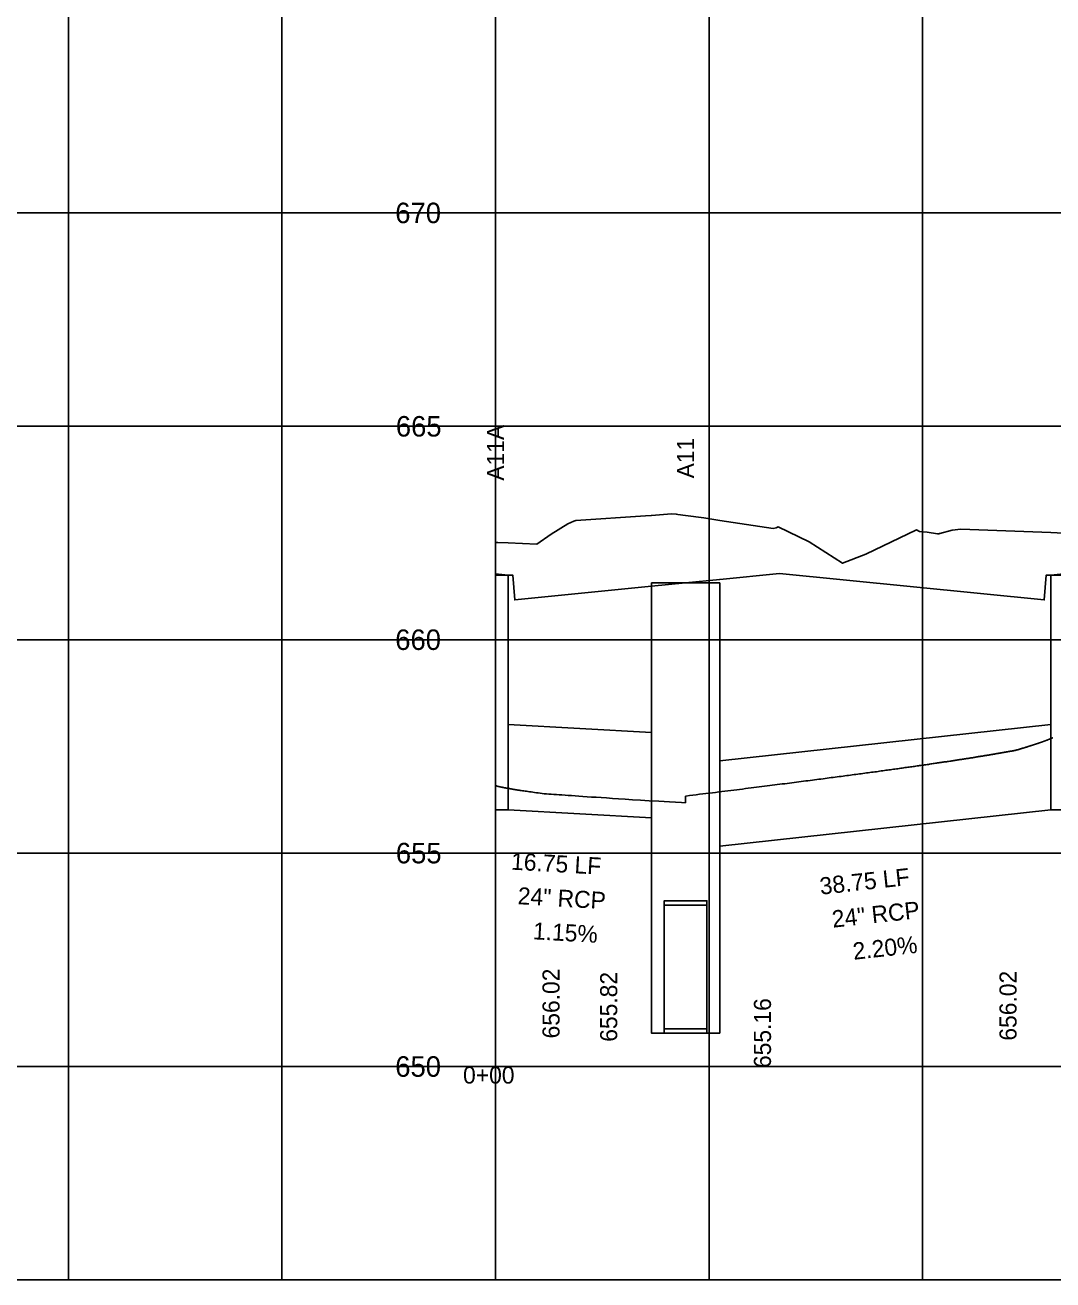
# Model space of a CAD drawing. Extents: x 2252703 to 2264864, y 13787568 to 13790989.
# Drawn here: x 2264558.6 to 2264678.9, y 13789015.9 to 13789162.9 of the extents above; entities that cross this region are included whole.
import ezdxf

# ---------------------------------------------------------------- set-up
doc = ezdxf.new("R2010")
doc.units = 0
for name, color, linetype in [('blank4', 7, 'Continuous'), ('BORD_grid_bottom_major_5int', 7, 'Continuous'), ('D_DRN_PROF_HGL', 7, 'Continuous'), ('D_PROF_1', 7, 'Continuous'), ('D_PROF_NOTES_1', 7, 'Continuous'), ('Default', 7, 'Continuous'), ('Drain_PipeInside', 7, 'Continuous'), ('E_Terrain', 7, 'Continuous'), ('Inlet', 7, 'Continuous'), ('z - Construction', 7, 'Continuous')]:
    doc.layers.add(name, color=color, linetype=linetype)

msp = doc.modelspace()

# ---------------------------------------------------------------- linework, layer by layer
at = {"layer": 'blank4'}
msp.add_lwpolyline([(2264613.67, 13789040.93), (2264613.67, 13789140.93), (2264701.42, 13789140.93), (2264701.42, 13789040.93)], close=True, dxfattribs=at)
at = {"layer": 'BORD_grid_bottom_major_5int'}
for p, q in [((2264563.67, 13789015.93), (2264563.67, 13789315.93)), ((2264588.67, 13789015.93), (2264588.67, 13789315.93)), ((2264613.67, 13789015.93), (2264613.67, 13789315.93)), ((2264638.67, 13789015.93), (2264638.67, 13789315.93)), ((2264663.67, 13789015.93), (2264663.67, 13789315.93)), ((2264413.67, 13789140.93), (2264763.67, 13789140.93)), ((2264413.67, 13789115.93), (2264763.67, 13789115.93)), ((2264413.67, 13789090.93), (2264763.67, 13789090.93)), ((2264413.67, 13789065.93), (2264763.67, 13789065.93)), ((2264413.67, 13789040.93), (2264763.67, 13789040.93)), ((2264413.67, 13789015.93), (2264763.67, 13789015.93))]:
    msp.add_line(p, q, dxfattribs=at)
at = {"layer": 'D_DRN_PROF_HGL'}
msp.add_line((2264635.92, 13789071.81), (2264635.92, 13789072.61), dxfattribs=at)
for points in [[(2264635.92, 13789072.61), (2264635.95, 13789072.62), (2264636.36, 13789072.67), (2264636.76, 13789072.72), (2264637.15, 13789072.77), (2264637.54, 13789072.82), (2264637.93, 13789072.86), (2264638.31, 13789072.91), (2264638.69, 13789072.96), (2264639.06, 13789073), (2264639.43, 13789073.05), (2264639.8, 13789073.09), (2264640.16, 13789073.14), (2264640.52, 13789073.18), (2264640.87, 13789073.23), (2264641.22, 13789073.27), (2264641.57, 13789073.31), (2264641.91, 13789073.36), (2264642.25, 13789073.4), (2264642.59, 13789073.44), (2264642.92, 13789073.48), (2264643.25, 13789073.52), (2264643.58, 13789073.56), (2264643.9, 13789073.61), (2264644.22, 13789073.65), (2264644.53, 13789073.69), (2264644.85, 13789073.72), (2264645.16, 13789073.76), (2264645.46, 13789073.8), (2264645.77, 13789073.84), (2264646.07, 13789073.88), (2264646.37, 13789073.92), (2264646.66, 13789073.95), (2264646.95, 13789073.99), (2264647.24, 13789074.03), (2264647.53, 13789074.06), (2264647.81, 13789074.1), (2264648.1, 13789074.14), (2264648.37, 13789074.17), (2264648.65, 13789074.21), (2264648.92, 13789074.24), (2264649.19, 13789074.28), (2264649.46, 13789074.31), (2264649.73, 13789074.35), (2264649.99, 13789074.38), (2264650.25, 13789074.41), (2264650.51, 13789074.45), (2264650.77, 13789074.48), (2264651.02, 13789074.51), (2264651.27, 13789074.55), (2264651.52, 13789074.58), (2264651.77, 13789074.61), (2264652.01, 13789074.64), (2264652.26, 13789074.67), (2264652.5, 13789074.71), (2264652.74, 13789074.74), (2264652.97, 13789074.77), (2264653.21, 13789074.8), (2264653.44, 13789074.83), (2264653.67, 13789074.86), (2264653.9, 13789074.89), (2264654.12, 13789074.92), (2264654.35, 13789074.95), (2264654.57, 13789074.98), (2264654.79, 13789075.01), (2264655.01, 13789075.04), (2264655.22, 13789075.07), (2264655.44, 13789075.09), (2264655.65, 13789075.12), (2264655.86, 13789075.15), (2264656.07, 13789075.18), (2264656.28, 13789075.21), (2264656.48, 13789075.23), (2264656.69, 13789075.26), (2264656.89, 13789075.29), (2264657.09, 13789075.32), (2264657.29, 13789075.34), (2264657.49, 13789075.37), (2264657.68, 13789075.4), (2264657.88, 13789075.42), (2264658.07, 13789075.45), (2264658.26, 13789075.47), (2264658.45, 13789075.5), (2264658.64, 13789075.53), (2264658.82, 13789075.55), (2264659.01, 13789075.58), (2264659.19, 13789075.6), (2264659.37, 13789075.63), (2264659.55, 13789075.65), (2264659.73, 13789075.68), (2264659.91, 13789075.7), (2264660.08, 13789075.73), (2264660.26, 13789075.75), (2264660.43, 13789075.77), (2264660.6, 13789075.8), (2264660.77, 13789075.82), (2264660.94, 13789075.84), (2264661.11, 13789075.87), (2264661.27, 13789075.89), (2264661.44, 13789075.91), (2264661.6, 13789075.94), (2264661.77, 13789075.96), (2264661.93, 13789075.98), (2264662.09, 13789076.01), (2264662.24, 13789076.03), (2264662.4, 13789076.05), (2264662.56, 13789076.07), (2264662.71, 13789076.09), (2264662.87, 13789076.12), (2264663.02, 13789076.14), (2264663.17, 13789076.16), (2264663.32, 13789076.18), (2264663.47, 13789076.2), (2264663.62, 13789076.22), (2264663.76, 13789076.25), (2264663.91, 13789076.27), (2264664.05, 13789076.29), (2264664.19, 13789076.31), (2264664.34, 13789076.33), (2264664.48, 13789076.35), (2264664.62, 13789076.37), (2264664.76, 13789076.39), (2264664.89, 13789076.41), (2264665.03, 13789076.43), (2264665.17, 13789076.45), (2264665.3, 13789076.47), (2264665.43, 13789076.49), (2264665.57, 13789076.51), (2264665.7, 13789076.53), (2264665.83, 13789076.55), (2264665.96, 13789076.57), (2264666.09, 13789076.59), (2264666.21, 13789076.61), (2264666.34, 13789076.62), (2264666.47, 13789076.64), (2264666.59, 13789076.66), (2264666.71, 13789076.68), (2264666.84, 13789076.7), (2264666.96, 13789076.72), (2264667.08, 13789076.74), (2264667.2, 13789076.75), (2264667.32, 13789076.77), (2264667.44, 13789076.79), (2264667.55, 13789076.81), (2264667.67, 13789076.83), (2264667.79, 13789076.84), (2264667.9, 13789076.86), (2264668.02, 13789076.88), (2264668.13, 13789076.9), (2264668.24, 13789076.91), (2264668.35, 13789076.93), (2264668.46, 13789076.95), (2264668.57, 13789076.96), (2264668.68, 13789076.98), (2264668.79, 13789077), (2264668.9, 13789077.01), (2264669, 13789077.03), (2264669.11, 13789077.05), (2264669.21, 13789077.06), (2264669.32, 13789077.08), (2264669.42, 13789077.1), (2264669.52, 13789077.11), (2264669.62, 13789077.13), (2264669.72, 13789077.15), (2264669.82, 13789077.16), (2264669.92, 13789077.18), (2264670.02, 13789077.19), (2264670.12, 13789077.21), (2264670.22, 13789077.23), (2264670.31, 13789077.24), (2264670.41, 13789077.26), (2264670.5, 13789077.27), (2264670.6, 13789077.29), (2264670.69, 13789077.3), (2264670.79, 13789077.32), (2264670.88, 13789077.33), (2264670.97, 13789077.35), (2264671.06, 13789077.36), (2264671.15, 13789077.38), (2264671.24, 13789077.39), (2264671.33, 13789077.41), (2264671.42, 13789077.42), (2264671.5, 13789077.44), (2264671.59, 13789077.45), (2264671.68, 13789077.47), (2264671.76, 13789077.48), (2264671.85, 13789077.49), (2264671.93, 13789077.51), (2264672.01, 13789077.52), (2264672.1, 13789077.54), (2264672.18, 13789077.55), (2264672.26, 13789077.57), (2264672.34, 13789077.58), (2264672.42, 13789077.59), (2264672.5, 13789077.61), (2264672.58, 13789077.62), (2264672.66, 13789077.63), (2264672.74, 13789077.65), (2264672.82, 13789077.66), (2264672.89, 13789077.67), (2264672.97, 13789077.69), (2264673.04, 13789077.7), (2264673.12, 13789077.71), (2264673.19, 13789077.73), (2264673.27, 13789077.74), (2264673.34, 13789077.75), (2264673.41, 13789077.77), (2264673.49, 13789077.78), (2264673.56, 13789077.79), (2264673.63, 13789077.81), (2264673.7, 13789077.82), (2264673.77, 13789077.83), (2264673.84, 13789077.84), (2264673.91, 13789077.86), (2264673.98, 13789077.87), (2264674.05, 13789077.88), (2264674.11, 13789077.89), (2264674.18, 13789077.91), (2264674.25, 13789077.92), (2264674.31, 13789077.93), (2264674.38, 13789077.94), (2264674.44, 13789077.96), (2264674.51, 13789077.97), (2264674.57, 13789077.98), (2264674.63, 13789077.99), (2264674.7, 13789078.01), (2264674.76, 13789078.02), (2264674.82, 13789078.04), (2264674.88, 13789078.06), (2264674.94, 13789078.08), (2264675, 13789078.1), (2264675.06, 13789078.12), (2264675.12, 13789078.13), (2264675.18, 13789078.15), (2264675.24, 13789078.17), (2264675.3, 13789078.19), (2264675.36, 13789078.21), (2264675.41, 13789078.22), (2264675.47, 13789078.24), (2264675.53, 13789078.26), (2264675.58, 13789078.28), (2264675.64, 13789078.29), (2264675.69, 13789078.31), (2264675.75, 13789078.33), (2264675.8, 13789078.34), (2264675.85, 13789078.36), (2264675.91, 13789078.38), (2264675.96, 13789078.39), (2264676.01, 13789078.41), (2264676.06, 13789078.43), (2264676.11, 13789078.44), (2264676.17, 13789078.46), (2264676.22, 13789078.48), (2264676.27, 13789078.49), (2264676.32, 13789078.51), (2264676.36, 13789078.52), (2264676.41, 13789078.54), (2264676.46, 13789078.55), (2264676.51, 13789078.57), (2264676.56, 13789078.59), (2264676.6, 13789078.6), (2264676.65, 13789078.62), (2264676.7, 13789078.63), (2264676.74, 13789078.65), (2264676.79, 13789078.66), (2264676.83, 13789078.68), (2264676.88, 13789078.69), (2264676.92, 13789078.71), (2264676.97, 13789078.72), (2264677.01, 13789078.74), (2264677.06, 13789078.75), (2264677.1, 13789078.76), (2264677.14, 13789078.78), (2264677.18, 13789078.79), (2264677.22, 13789078.81), (2264677.27, 13789078.82), (2264677.31, 13789078.84), (2264677.35, 13789078.85), (2264677.39, 13789078.86), (2264677.43, 13789078.88), (2264677.47, 13789078.89), (2264677.51, 13789078.9), (2264677.55, 13789078.92), (2264677.58, 13789078.93), (2264677.62, 13789078.94), (2264677.66, 13789078.96), (2264677.7, 13789078.97), (2264677.73, 13789078.98), (2264677.77, 13789079), (2264677.81, 13789079.01), (2264677.84, 13789079.02), (2264677.88, 13789079.04), (2264677.91, 13789079.05), (2264677.95, 13789079.06), (2264677.98, 13789079.07), (2264678.02, 13789079.09), (2264678.05, 13789079.1), (2264678.09, 13789079.11), (2264678.12, 13789079.12), (2264678.15, 13789079.14), (2264678.19, 13789079.15), (2264678.22, 13789079.16), (2264678.25, 13789079.17), (2264678.28, 13789079.18), (2264678.31, 13789079.2), (2264678.34, 13789079.21), (2264678.38, 13789079.22), (2264678.41, 13789079.23), (2264678.44, 13789079.24), (2264678.47, 13789079.26), (2264678.5, 13789079.27), (2264678.52, 13789079.28), (2264678.55, 13789079.29), (2264678.58, 13789079.3), (2264678.61, 13789079.31), (2264678.64, 13789079.32), (2264678.67, 13789079.33), (2264678.69, 13789079.35), (2264678.72, 13789079.36), (2264678.75, 13789079.37), (2264678.77, 13789079.38), (2264678.8, 13789079.39), (2264678.83, 13789079.4), (2264678.85, 13789079.41), (2264678.88, 13789079.42), (2264678.9, 13789079.43), (2264678.93, 13789079.44)], [(2264613.67, 13789074.75), (2264613.67, 13789073.89), (2264613.67, 13789073.88), (2264613.68, 13789073.88), (2264613.68, 13789073.87), (2264613.68, 13789073.87), (2264613.69, 13789073.86), (2264613.7, 13789073.85), (2264613.71, 13789073.85), (2264613.72, 13789073.84), (2264613.73, 13789073.84), (2264613.74, 13789073.83), (2264613.76, 13789073.82), (2264613.77, 13789073.82), (2264613.79, 13789073.81), (2264613.81, 13789073.8), (2264613.83, 13789073.79), (2264613.85, 13789073.79), (2264613.87, 13789073.78), (2264613.9, 13789073.77), (2264613.92, 13789073.76), (2264613.95, 13789073.75), (2264613.98, 13789073.75), (2264614.02, 13789073.74), (2264614.05, 13789073.73), (2264614.09, 13789073.72), (2264614.13, 13789073.71), (2264614.17, 13789073.7), (2264614.21, 13789073.69), (2264614.25, 13789073.68), (2264614.3, 13789073.67), (2264614.35, 13789073.66), (2264614.4, 13789073.65), (2264614.45, 13789073.64), (2264614.51, 13789073.63), (2264614.57, 13789073.61), (2264614.63, 13789073.6), (2264614.69, 13789073.59), (2264614.76, 13789073.58), (2264614.83, 13789073.56), (2264614.9, 13789073.55), (2264614.98, 13789073.54), (2264615.06, 13789073.52), (2264615.14, 13789073.51), (2264615.22, 13789073.49), (2264615.31, 13789073.48), (2264615.4, 13789073.46), (2264615.5, 13789073.45), (2264615.6, 13789073.43), (2264615.7, 13789073.41), (2264615.81, 13789073.4), (2264615.92, 13789073.38), (2264616.04, 13789073.36), (2264616.16, 13789073.34), (2264616.28, 13789073.32), (2264616.42, 13789073.3), (2264616.55, 13789073.28), (2264616.69, 13789073.26), (2264616.84, 13789073.24), (2264616.99, 13789073.22), (2264617.15, 13789073.19), (2264617.31, 13789073.17), (2264617.48, 13789073.14), (2264617.66, 13789073.12), (2264617.85, 13789073.09), (2264618.04, 13789073.07), (2264618.24, 13789073.04), (2264618.45, 13789073.01), (2264618.67, 13789072.98), (2264618.89, 13789072.95), (2264619.13, 13789072.92), (2264619.38, 13789072.89), (2264619.63, 13789072.87), (2264619.9, 13789072.85), (2264620.19, 13789072.83), (2264620.48, 13789072.81), (2264620.79, 13789072.79), (2264621.11, 13789072.76), (2264621.45, 13789072.74), (2264621.81, 13789072.72), (2264622.18, 13789072.69), (2264622.57, 13789072.66), (2264622.99, 13789072.63), (2264623.43, 13789072.6), (2264623.89, 13789072.57), (2264624.38, 13789072.54), (2264624.9, 13789072.5), (2264625.45, 13789072.47), (2264626.04, 13789072.43), (2264626.67, 13789072.39), (2264627.35, 13789072.34), (2264628.07, 13789072.3), (2264628.86, 13789072.25), (2264629.71, 13789072.19), (2264630.64, 13789072.13), (2264631.66, 13789072.07), (2264632.78, 13789072), (2264634.03, 13789071.92), (2264635.44, 13789071.84), (2264635.92, 13789071.81)]]:
    msp.add_lwpolyline(points, dxfattribs=at)
at = {"layer": 'D_PROF_1'}
msp.add_lwpolyline([(2264613.67, 13789098.66), (2264615.17, 13789098.51), (2264615.17, 13789098.51), (2264615.17, 13789098.51), (2264615.69, 13789098.51), (2264615.92, 13789095.59), (2264631.92, 13789097.19), (2264631.92, 13789097.19), (2264635.92, 13789097.59), (2264635.92, 13789097.59), (2264639.92, 13789097.99), (2264639.92, 13789097.99), (2264646.92, 13789098.69), (2264677.92, 13789095.59), (2264678.15, 13789098.51), (2264678.67, 13789098.51), (2264678.67, 13789098.51), (2264680.17, 13789098.66)], dxfattribs=at)
at = {"layer": 'Drain_PipeInside'}
for p, q in [((2264615.17, 13789081.01), (2264631.92, 13789080.05)), ((2264639.92, 13789076.75), (2264678.67, 13789081.01)), ((2264615.17, 13789071.01), (2264631.92, 13789070.05)), ((2264639.92, 13789066.75), (2264678.67, 13789071.01))]:
    msp.add_line(p, q, dxfattribs=at)
for points in [[(2264633.42, 13789045.34), (2264638.42, 13789045.34), (2264638.42, 13789060.34), (2264633.42, 13789060.34)], [(2264633.42, 13789044.84), (2264638.42, 13789044.84), (2264638.42, 13789059.84), (2264633.42, 13789059.84)]]:
    msp.add_lwpolyline(points, close=True, dxfattribs=at)
at = {"layer": 'E_Terrain'}
msp.add_lwpolyline([(2264613.67, 13789102.32), (2264613.94, 13789102.32), (2264615.17, 13789102.27), (2264615.17, 13789102.27), (2264618.51, 13789102.12), (2264620.18, 13789103.28), (2264622.14, 13789104.51), (2264622.85, 13789104.8), (2264623.06, 13789104.88), (2264631.23, 13789105.43), (2264631.92, 13789105.49), (2264631.92, 13789105.49), (2264634.28, 13789105.69), (2264634.82, 13789105.65), (2264635, 13789105.61), (2264635.92, 13789105.48), (2264635.92, 13789105.48), (2264638.07, 13789105.19), (2264639.92, 13789104.9), (2264639.92, 13789104.9), (2264646.16, 13789103.95), (2264646.51, 13789104.03), (2264646.75, 13789104.14), (2264650.39, 13789102.38), (2264654.31, 13789099.89), (2264657.02, 13789100.95), (2264662.97, 13789103.81), (2264663.31, 13789103.62), (2264664.2, 13789103.51), (2264665.4, 13789103.33), (2264665.45, 13789103.34), (2264665.47, 13789103.34), (2264665.49, 13789103.34), (2264665.56, 13789103.35), (2264665.66, 13789103.36), (2264665.67, 13789103.36), (2264667.13, 13789103.77), (2264668.14, 13789103.89), (2264678.67, 13789103.48), (2264678.67, 13789103.48), (2264680.17, 13789103.42)], dxfattribs=at)
at = {"layer": 'Inlet'}
for points in [[(2264613.67, 13789098.51), (2264615.17, 13789098.51), (2264615.17, 13789071.01), (2264613.67, 13789071.01)], [(2264678.67, 13789098.51), (2264681.67, 13789098.51), (2264681.67, 13789071.01), (2264678.67, 13789071.01)], [(2264631.92, 13789097.59), (2264639.92, 13789097.59), (2264639.92, 13789044.84), (2264631.92, 13789044.84)]]:
    msp.add_lwpolyline(points, close=True, dxfattribs=at)
at = {"layer": 'z - Construction'}
for p, q in [((2264613.67, 13789115.93), (2264701.42, 13789115.93)), ((2264613.67, 13789090.93), (2264701.42, 13789090.93)), ((2264613.67, 13789065.93), (2264701.42, 13789065.93))]:
    msp.add_line(p, q, dxfattribs=at)

# ---------------------------------------------------------------- texts
at = {"layer": 'D_PROF_NOTES_1'}
for s, rotation, p in [('A11A', 90, (2264614.67, 13789109.56)), ('A11', 90, (2264636.92, 13789109.83)), ('16.75 LF', 356.7198, (2264615.45, 13789064)), ('38.75 LF', 6.2773, (2264651.73, 13789061.05)), ('24" RCP', 356.7198, (2264616.23, 13789059.95)), ('24" RCP', 6.2773, (2264653.17, 13789057.19)), ('1.15%', 356.7198, (2264618.01, 13789055.84)), ('2.20%', 6.2773, (2264655.61, 13789053.43)), ('656.02', 90, (2264621.17, 13789044.22)), ('655.82', 90, (2264627.92, 13789043.83)), ('656.02', 90, (2264674.67, 13789043.96)), ('655.16', 90, (2264645.92, 13789040.75))]:
    msp.add_text(s, height=2, rotation=rotation, dxfattribs=at).set_placement(p)
at = {"layer": 'Default'}
for s, height, p in [('670', 2.4, (2264601.93, 13789139.73)), ('665', 2.4, (2264602, 13789114.73)), ('660', 2.4, (2264601.93, 13789089.73)), ('655', 2.4, (2264602, 13789064.73)), ('650', 2.4, (2264601.93, 13789039.73)), ('0+00', 2, (2264609.87, 13789038.93))]:
    msp.add_text(s, height=height, dxfattribs=at).set_placement(p)

doc.saveas('drawing.dxf')
